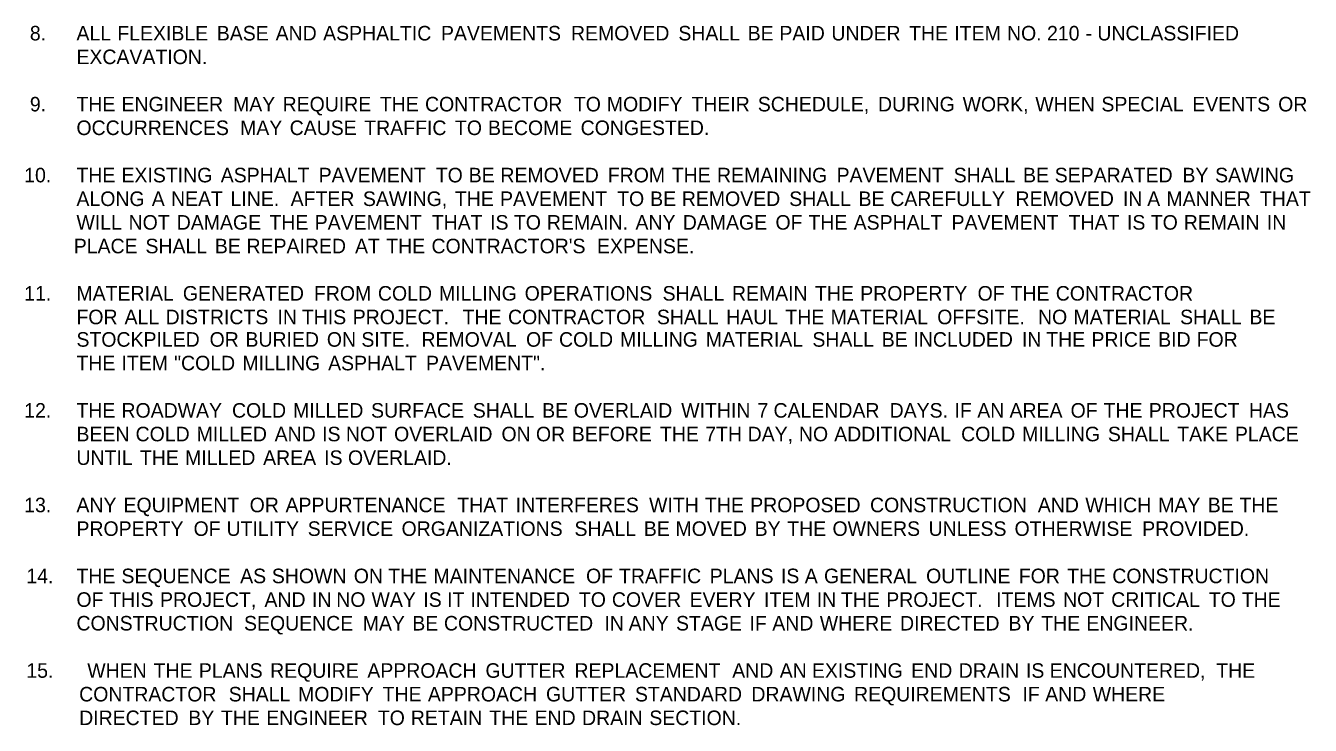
# Model space of a CAD drawing. Extents: x 1930579 to 1932220, y 596452 to 599479.
# Drawn here: x 1930762 to 1931345, y 598759 to 599076 of the extents above; entities that cross this region are included whole.
import ezdxf

# ---------------------------------------------------------------- set-up
doc = ezdxf.new("R2010")
doc.units = 0
doc.layers.add('Default', color=7, linetype='Continuous')

msp = doc.modelspace()

# ---------------------------------------------------------------- texts
at = {"layer": 'Default'}
for s, p in [('8.', (1930764.2, 599069.35)), ('ALL', (1930785.33, 599069.35)), (' FLEXIBLE', (1930801.41, 599069.35)), (' BASE', (1930846.53, 599069.35)), (' AND', (1930873.21, 599069.35)), (' ASPHALTIC', (1930894.75, 599069.35)), (' PAVEMENTS', (1930948.2, 599069.35)), (' REMOVED', (1931007.16, 599069.35)), (' SHALL', (1931055.86, 599069.35)), (' BE', (1931087.31, 599069.35)), (' PAID', (1931101.69, 599069.35)), (' UNDER', (1931125.28, 599069.35)), (' THE', (1931160.51, 599069.35)), (' ITEM', (1931181.02, 599069.35)), (' NO.', (1931204.92, 599069.35)), (' 210', (1931223.07, 599069.35)), (' -', (1931240.56, 599069.35)), (' UNCLASSIFIED', (1931245.9, 599069.35)), ('EXCAVATION.', (1930785.33, 599058.62)), ('9.', (1930764.2, 599037.17)), ('THE', (1930785.33, 599037.17)), (' ENGINEER', (1930803.29, 599037.17)), (' MAY', (1930853.89, 599037.17)), (' REQUIRE', (1930876.37, 599037.17)), (' THE', (1930920.46, 599037.17)), (' CONTRACTOR', (1930940.97, 599037.17)), (' TO', (1931008.48, 599037.17)), (' MODIFY', (1931023.43, 599037.17)), (' THEIR', (1931061.78, 599037.17)), (' SCHEDULE,', (1931091.89, 599037.17)), (' DURING', (1931146.41, 599037.17)), (' WORK,', (1931184.77, 599037.17)), (' WHEN', (1931217.76, 599037.17)), (' SPECIAL', (1931247.74, 599037.17)), (' EVENTS', (1931288.93, 599037.17)), (' OR', (1931327.91, 599037.17)), ('OCCURRENCES', (1930785.33, 599026.45)), (' MAY', (1930857.1, 599026.45)), (' CAUSE', (1930879.58, 599026.45)), (' TRAFFIC', (1930913.42, 599026.45)), (' TO', (1930954.55, 599026.45)), (' BECOME', (1930969.51, 599026.45)), (' CONGESTED.', (1931011.55, 599026.45)), ('10.', (1930761.63, 599005)), ('THE', (1930785.33, 599005)), (' EXISTING', (1930803.29, 599005)), (' ASPHALT', (1930848.31, 599005)), (' PAVEMENT', (1930892.72, 599005)), (' TO', (1930945.83, 599005)), (' BE', (1930960.79, 599005)), (' REMOVED', (1930975.16, 599005)), (' FROM', (1931023.86, 599005)), (' THE', (1931052.87, 599005)), (' REMAINING', (1931073.39, 599005)), (' PAVEMENT', (1931127.63, 599005)), (' SHALL', (1931180.74, 599005)), (' BE', (1931212.2, 599005)), (' SEPARATED', (1931226.57, 599005)), (' BY', (1931284.5, 599005)), (' SAWING', (1931299.3, 599005)), ('ALONG', (1930785.33, 598994.27)), (' A', (1930817.04, 598994.27)), (' NEAT', (1930825.77, 598994.27)), (' LINE.', (1930852.74, 598994.27)), ('  AFTER', (1930877.56, 598994.27)), (' SAWING,', (1930912.79, 598994.27)), (' THE', (1930954.49, 598994.27)), (' PAVEMENT', (1930975, 598994.27)), (' TO', (1931028.11, 598994.27)), (' BE', (1931043.07, 598994.27)), (' REMOVED', (1931057.44, 598994.27)), (' SHALL', (1931106.14, 598994.27)), (' BE', (1931137.59, 598994.27)), (' CAREFULLY', (1931151.97, 598994.27)), (' REMOVED', (1931208.78, 598994.27)), (' IN', (1931257.48, 598994.27)), (' A', (1931268.51, 598994.27)), (' MANNER', (1931277.23, 598994.27)), (' THAT', (1931319.64, 598994.27)), ('WILL', (1930785.33, 598983.55)), (' NOT', (1930806.52, 598983.55)), (' DAMAGE', (1930828.36, 598983.55)), (' THE', (1930870.4, 598983.55)), (' PAVEMENT', (1930890.92, 598983.55)), (' THAT', (1930944.03, 598983.55)), (' IS', (1930970.49, 598983.55)), (' TO', (1930981.28, 598983.55)), (' REMAIN.', (1930996.23, 598983.55)), (' ANY', (1931036.41, 598983.55)), (' DAMAGE', (1931057.87, 598983.55)), (' OF', (1931099.91, 598983.55)), (' THE', (1931114.86, 598983.55)), (' ASPHALT', (1931135.37, 598983.55)), (' PAVEMENT', (1931179.77, 598983.55)), (' THAT', (1931232.89, 598983.55)), (' IS', (1931259.34, 598983.55)), (' TO', (1931270.13, 598983.55)), (' REMAIN', (1931285.09, 598983.55)), (' IN', (1931322.76, 598983.55)), ('   PLACE', (1930776.75, 598972.82)), (' SHALL', (1930814.18, 598972.82)), (' BE', (1930845.64, 598972.82)), (' REPAIRED', (1930860.01, 598972.82)), (' AT', (1930909.23, 598972.82)), (' THE', (1930923.39, 598972.82)), (" CONTRACTOR'S", (1930943.9, 598972.82)), (' EXPENSE.', (1931018.96, 598972.82)), ('11.', (1930761.63, 598951.37)), ('MATERIAL', (1930785.33, 598951.37)), (' GENERATED', (1930831.13, 598951.37)), (' FROM', (1930890.59, 598951.37)), (' COLD', (1930919.61, 598951.37)), (' MILLING', (1930947.29, 598951.37)), (' OPERATIONS', (1930986.17, 598951.37)), (' SHALL', (1931048.71, 598951.37)), (' REMAIN', (1931080.16, 598951.37)), (' THE', (1931117.84, 598951.37)), (' PROPERTY', (1931138.35, 598951.37)), (' OF', (1931191.58, 598951.37)), (' THE', (1931206.53, 598951.37)), (' CONTRACTOR', (1931227.04, 598951.37)), ('FOR', (1930785.33, 598940.65)), (' ALL', (1930804.68, 598940.65)), (' DISTRICTS', (1930823.31, 598940.65)), (' IN', (1930874.07, 598940.65)), (' THIS', (1930885.09, 598940.65)), (' PROJECT.', (1930908.18, 598940.65)), ('  THE', (1930955.54, 598940.65)), (' CONTRACTOR', (1930978.61, 598940.65)), (' SHALL', (1931046.12, 598940.65)), (' HAUL', (1931077.57, 598940.65)), (' THE', (1931104.4, 598940.65)), (' MATERIAL', (1931124.92, 598940.65)), (' OFFSITE.', (1931173.27, 598940.65)), ('  NO', (1931216.53, 598940.65)), (' MATERIAL', (1931235.07, 598940.65)), (' SHALL', (1931283.42, 598940.65)), (' BE', (1931314.87, 598940.65)), ('STOCKPILED', (1930785.33, 598930.46)), (' OR', (1930843.26, 598930.46)), (' BURIED', (1930859.53, 598930.46)), (' ON', (1930896.45, 598930.46)), (' SITE.', (1930912.09, 598930.46)), ('  REMOVAL', (1930936.9, 598930.46)), (' OF', (1930986.79, 598930.46)), (' COLD', (1931001.74, 598930.46)), (' MILLING', (1931029.43, 598930.46)), (' MATERIAL', (1931068.3, 598930.46)), (' SHALL', (1931116.65, 598930.46)), (' BE', (1931148.1, 598930.46)), (' INCLUDED', (1931162.47, 598930.46)), (' IN', (1931211.68, 598930.46)), (' THE', (1931222.71, 598930.46)), (' PRICE', (1931243.22, 598930.46)), (' BID', (1931273.48, 598930.46)), (' FOR', (1931290.92, 598930.46)), ('THE', (1930785.33, 598919.74)), (' ITEM', (1930803.29, 598919.74)), (' "COLD', (1930827.18, 598919.74)), (' MILLING', (1930858.14, 598919.74)), (' ASPHALT', (1930897.01, 598919.74)), (' PAVEMENT".', (1930941.42, 598919.74)), ('12.', (1930761.63, 598898.29)), ('THE', (1930785.33, 598898.29)), (' ROADWAY', (1930803.29, 598898.29)), (' COLD', (1930853.43, 598898.29)), (' MILLED', (1930881.12, 598898.29)), (' SURFACE', (1930916.49, 598898.29)), (' SHALL', (1930962.63, 598898.29)), (' BE', (1930994.08, 598898.29)), (' OVERLAID', (1931008.46, 598898.29)), (' WITHIN', (1931057.16, 598898.29)), (' 7', (1931091.75, 598898.29)), (' CALENDAR', (1931099.01, 598898.29)), (' DAYS.', (1931151.67, 598898.29)), (' IF', (1931181.11, 598898.29)), (' AN', (1931191.44, 598898.29)), (' AREA', (1931206.06, 598898.29)), (' OF', (1931233.75, 598898.29)), (' THE', (1931248.7, 598898.29)), (' PROJECT', (1931269.21, 598898.29)), (' HAS', (1931314.63, 598898.29)), ('BEEN', (1930785.33, 598887.56)), (' COLD', (1930809.7, 598887.56)), (' MILLED', (1930837.38, 598887.56)), (' AND', (1930872.76, 598887.56)), (' IS', (1930894.3, 598887.56)), (' NOT', (1930905.09, 598887.56)), (' OVERLAID', (1930926.93, 598887.56)), (' ON', (1930975.64, 598887.56)), (' OR', (1930991.28, 598887.56)), (' BEFORE', (1931007.54, 598887.56)), (' THE', (1931047.54, 598887.56)), (' 7TH', (1931068.05, 598887.56)), (' DAY,', (1931087.29, 598887.56)), (' NO', (1931110.55, 598887.56)), (' ADDITIONAL', (1931126.54, 598887.56)), (' COLD', (1931184.11, 598887.56)), (' MILLING', (1931211.8, 598887.56)), (' SHALL', (1931250.67, 598887.56)), (' TAKE', (1931282.12, 598887.56)), (' PLACE', (1931308.28, 598887.56)), ('UNTIL', (1930785.33, 598876.84)), (' THE', (1930811.65, 598876.84)), (' MILLED', (1930832.16, 598876.84)), (' AREA', (1930867.54, 598876.84)), (' IS', (1930895.23, 598876.84)), (' OVERLAID.', (1930906.02, 598876.84)), ('13.', (1930761.63, 598855.39)), ('ANY', (1930785.33, 598855.39)), (' EQUIPMENT', (1930804.23, 598855.39)), (' OR', (1930861.43, 598855.39)), (' APPURTENANCE', (1930877.7, 598855.39)), (' THAT', (1930955.62, 598855.39)), (' INTERFERES', (1930982.07, 598855.39)), (' WITH', (1931042.57, 598855.39)), (' THE', (1931067.94, 598855.39)), (' PROPOSED', (1931088.46, 598855.39)), (' CONSTRUCTION', (1931142.8, 598855.39)), (' AND', (1931218.9, 598855.39)), (' WHICH', (1931240.44, 598855.39)), (' MAY', (1931273.5, 598855.39)), (' BE', (1931295.97, 598855.39)), (' THE', (1931310.34, 598855.39)), ('PROPERTY', (1930785.33, 598844.66)), (' OF', (1930836, 598844.66)), (' UTILITY', (1930850.95, 598844.66)), (' SERVICE', (1930887.76, 598844.66)), (' ORGANIZATIONS', (1930930.32, 598844.66)), (' SHALL', (1931008.75, 598844.66)), (' BE', (1931040.2, 598844.66)), (' MOVED', (1931054.57, 598844.66)), (' BY', (1931090.46, 598844.66)), (' THE', (1931105.25, 598844.66)), (' OWNERS', (1931125.77, 598844.66)), (' UNLESS', (1931169.35, 598844.66)), (' OTHERWISE', (1931208.33, 598844.66)), (' PROVIDED.', (1931266.24, 598844.66)), ('14.', (1930762.6, 598823.21)), ('THE', (1930785.33, 598823.21)), (' SEQUENCE', (1930803.29, 598823.21)), (' AS', (1930857.12, 598823.21)), (' SHOWN', (1930871.5, 598823.21)), (' ON', (1930908.66, 598823.21)), (' THE', (1930924.3, 598823.21)), (' MAINTENANCE', (1930944.81, 598823.21)), (' OF', (1931014, 598823.21)), (' TRAFFIC', (1931028.95, 598823.21)), (' PLANS', (1931070.08, 598823.21)), (' IS', (1931102.4, 598823.21)), (' A', (1931113.19, 598823.21)), (' GENERAL', (1931121.92, 598823.21)), (' OUTLINE', (1931168.23, 598823.21)), (' FOR', (1931210.26, 598823.21)), (' THE', (1931232.17, 598823.21)), (' CONSTRUCTION', (1931252.68, 598823.21)), ('OF', (1930785.33, 598812.49)), (' THIS', (1930797.72, 598812.49)), (' PROJECT,', (1930820.8, 598812.49)), (' AND', (1930868.15, 598812.49)), (' IN', (1930889.69, 598812.49)), (' NO', (1930900.72, 598812.49)), (' WAY', (1930916.7, 598812.49)), (' IS', (1930940.2, 598812.49)), (' IT', (1930950.99, 598812.49)), (' INTENDED', (1930961.56, 598812.49)), (' TO', (1931010.76, 598812.49)), (' COVER', (1931025.72, 598812.49)), (' EVERY', (1931060.95, 598812.49)), (' ITEM', (1931094.71, 598812.49)), (' IN', (1931118.61, 598812.49)), (' THE', (1931129.63, 598812.49)), (' PROJECT.', (1931150.15, 598812.49)), ('  ITEMS', (1931197.51, 598812.49)), (' NOT', (1931230.33, 598812.49)), (' CRITICAL', (1931252.17, 598812.49)), (' TO', (1931296.42, 598812.49)), (' THE', (1931311.38, 598812.49)), ('CONSTRUCTION', (1930785.33, 598801.76)), (' SEQUENCE', (1930858.87, 598801.76)), (' CONSTRUCTED', (1930949.55, 598801.76)), (' STAGE', (1931054.81, 598801.76)), (' DIRECTED', (1931156.41, 598801.76)), (' ENGINEER.', (1931240.92, 598801.76)), (' MAY', (1930912.7, 598801.76)), (' BE', (1930935.18, 598801.76)), (' IN', (1931022.32, 598801.76)), (' ANY', (1931033.35, 598801.76)), (' IF', (1931088.14, 598801.76)), (' AND', (1931098.47, 598801.76)), (' WHERE', (1931120.01, 598801.76)), (' BY', (1931205.62, 598801.76)), (' THE', (1931220.41, 598801.76)), ('15.', (1930762.6, 598780.31)), ('  WHEN', (1930785.33, 598780.31)), (' THE', (1930817.88, 598780.31)), (' PLANS', (1930838.39, 598780.31)), (' REQUIRE', (1930870.71, 598780.31)), (' APPROACH', (1930914.8, 598780.31)), (' GUTTER', (1930968.38, 598780.31)), (' REPLACEMENT', (1931008.73, 598780.31)), (' AND', (1931080.29, 598780.31)), (' AN', (1931101.83, 598780.31)), (' EXISTING', (1931116.44, 598780.31)), (' END', (1931161.47, 598780.31)), (' DRAIN', (1931183.01, 598780.31)), (' IS', (1931213.51, 598780.31)), (' ENCOUNTERED,', (1931224.3, 598780.31)), (' THE', (1931299.83, 598780.31)), ('    CONTRACTOR', (1930776.75, 598769.59)), (' SHALL', (1930851.94, 598769.59)), (' MODIFY', (1930883.39, 598769.59)), (' THE', (1930921.74, 598769.59)), (' APPROACH', (1930942.26, 598769.59)), (' GUTTER', (1930995.84, 598769.59)), (' STANDARD', (1931036.19, 598769.59)), (' DRAWING', (1931088.99, 598769.59)), (' REQUIREMENTS', (1931135.54, 598769.59)), (' IF', (1931211.92, 598769.59)), (' AND', (1931222.25, 598769.59)), (' WHERE', (1931243.79, 598769.59)), ('    DIRECTED', (1930776.75, 598758.86)), (' BY', (1930833.64, 598758.86)), (' THE', (1930848.44, 598758.86)), (' ENGINEER', (1930868.95, 598758.86)), (' TO', (1930919.56, 598758.86)), (' RETAIN', (1930934.51, 598758.86)), (' THE', (1930970.14, 598758.86)), (' END', (1930990.65, 598758.86)), (' DRAIN', (1931012.19, 598758.86)), (' SECTION.', (1931042.69, 598758.86))]:
    msp.add_text(s, height=6.6, dxfattribs=at).set_placement(p)

doc.saveas('drawing.dxf')
